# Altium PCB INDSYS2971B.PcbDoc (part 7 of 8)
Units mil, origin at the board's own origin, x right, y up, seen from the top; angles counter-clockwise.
Board outline 6450 x 5820 mil, 6 copper layers (Top Layer, Int1 (PGND), Int2 (AGND), Int3 (Signal), Int4 (PGND), Bottom Layer), stack 70.536 mil thick; 787 components, 431 nets, 2530 pads, 2497 vias.
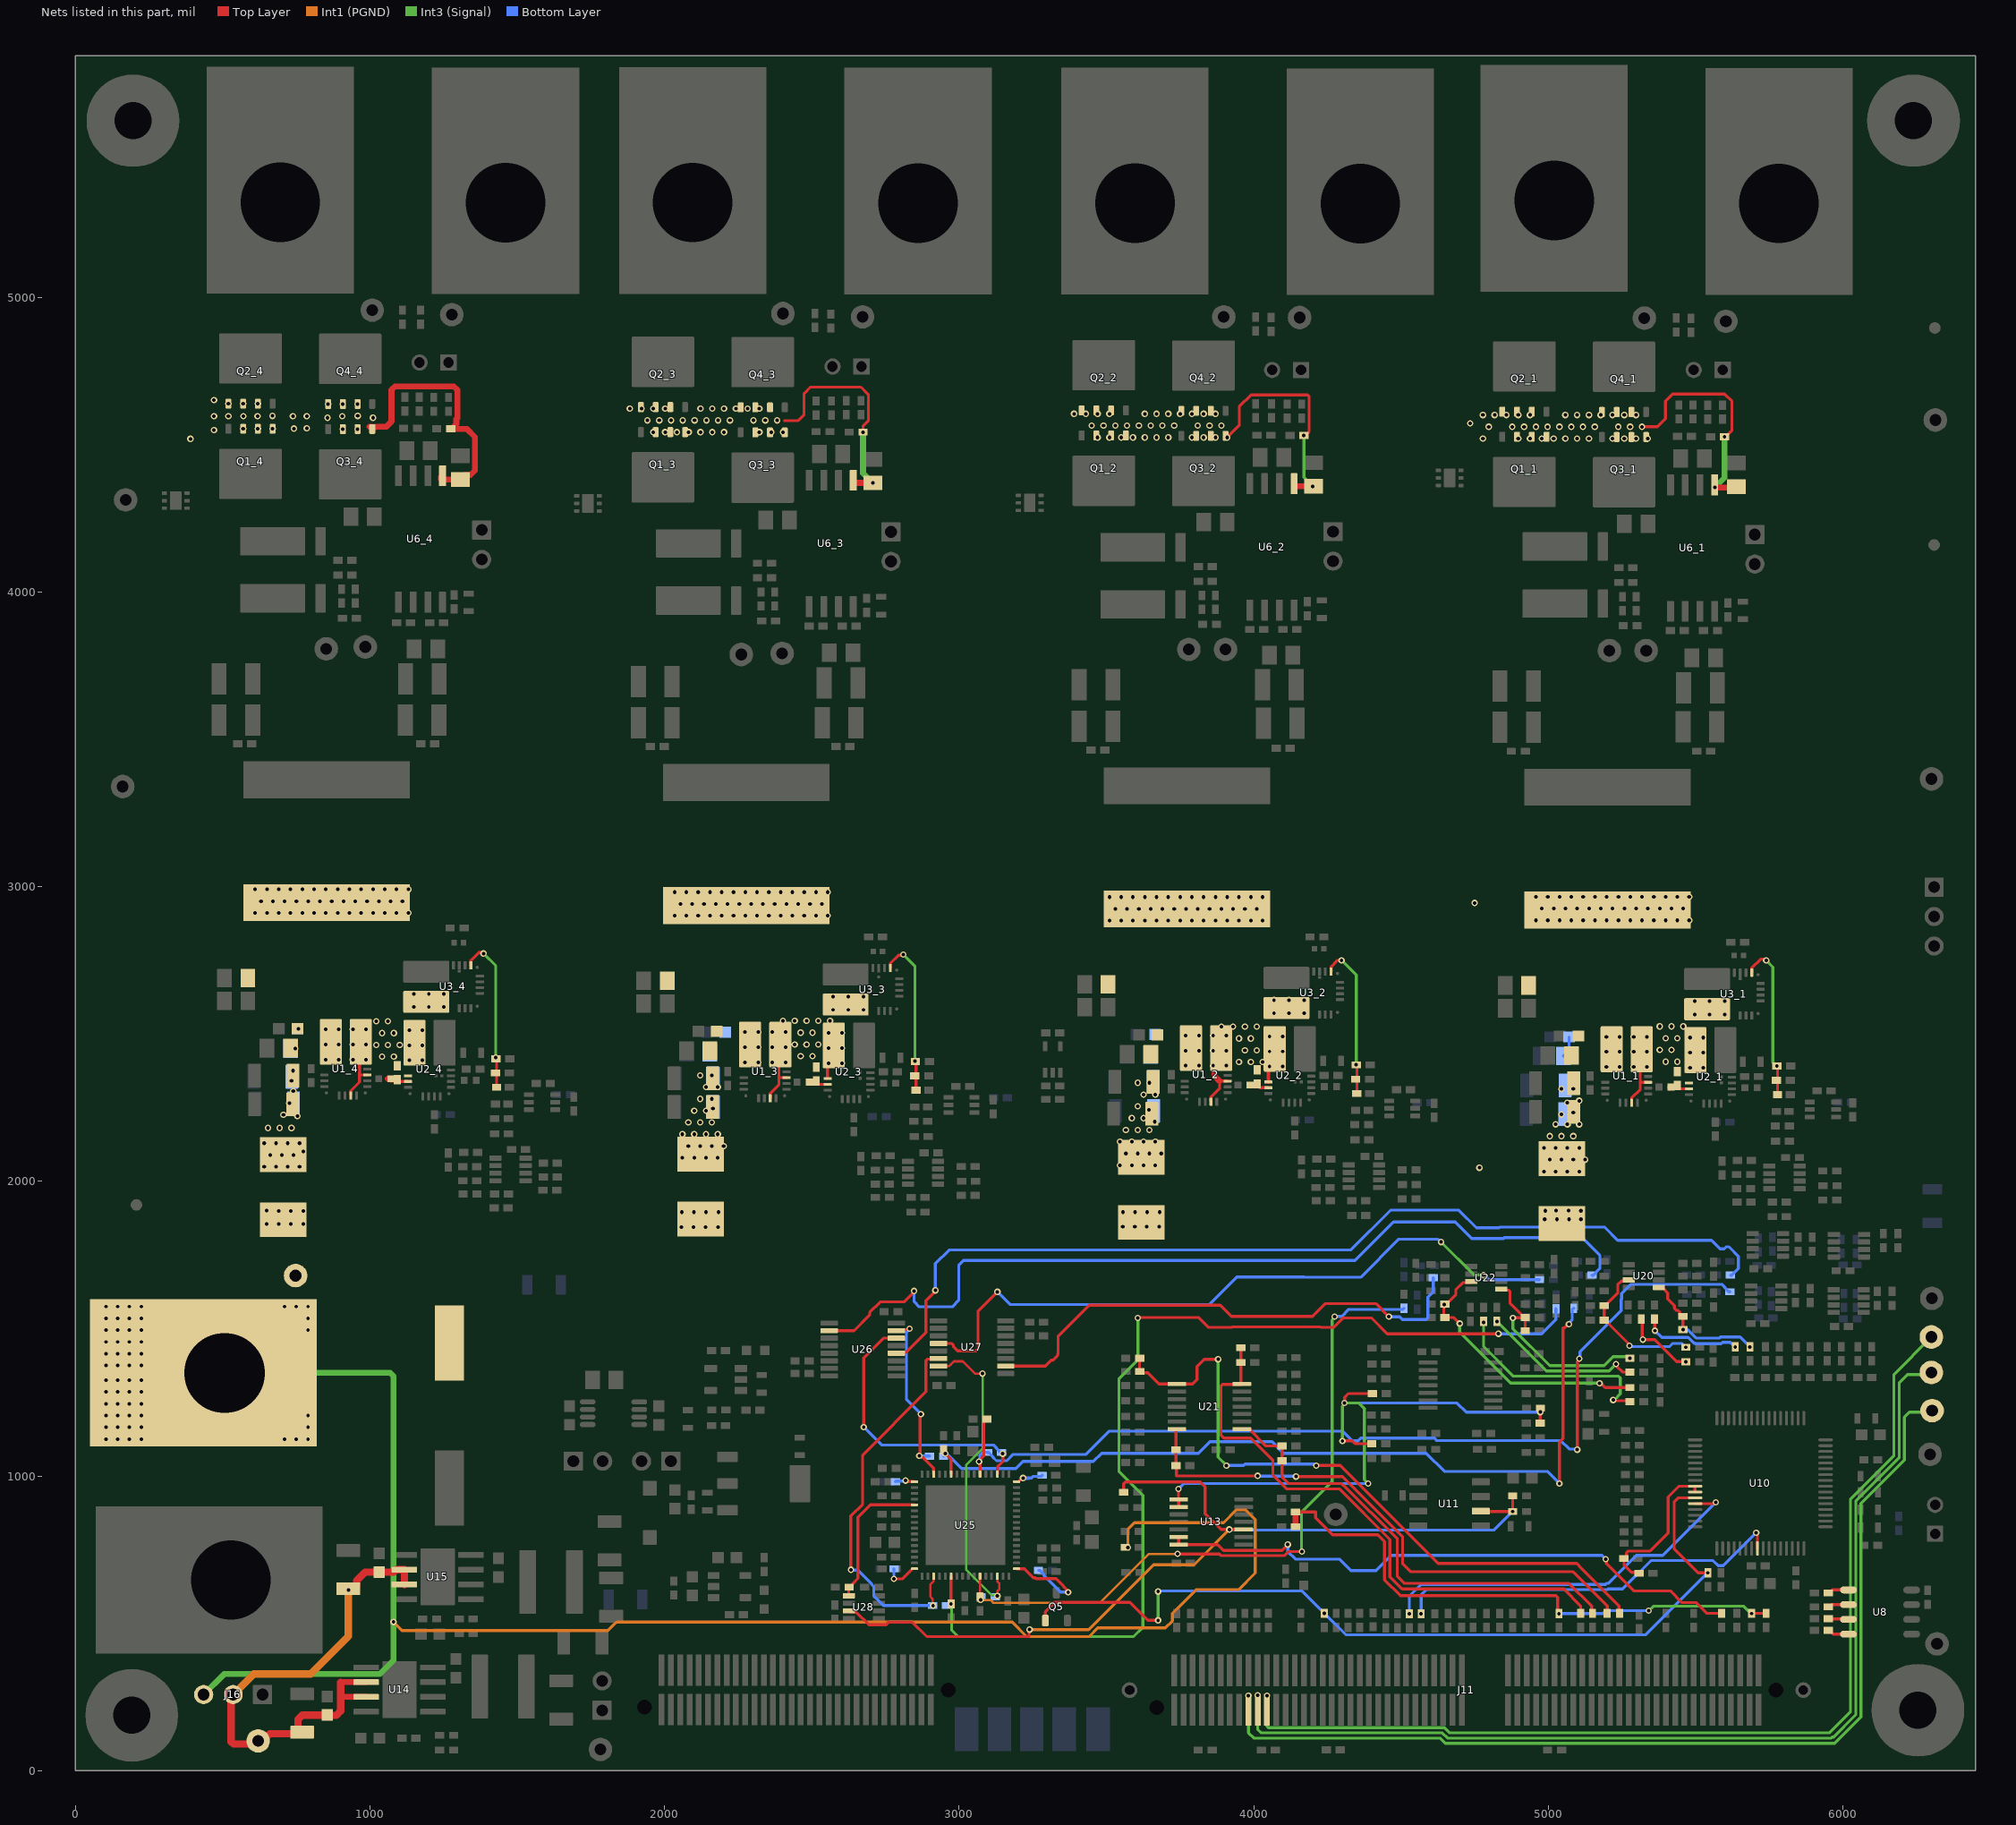
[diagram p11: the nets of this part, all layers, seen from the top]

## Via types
v1: diameter 22, hole 12.5, Top Layer to Bottom Layer, 873 vias
v2: diameter 22, hole 12, Top Layer to Bottom Layer, tented both sides, 788 vias
v3: diameter 22, hole 12, Top Layer to Bottom Layer, 586 vias
v4: diameter 22, hole 12.5, Top Layer to Bottom Layer, tented both sides, 249 vias
v5: diameter 24, hole 12, Top Layer to Bottom Layer, tented both sides, 1 vias

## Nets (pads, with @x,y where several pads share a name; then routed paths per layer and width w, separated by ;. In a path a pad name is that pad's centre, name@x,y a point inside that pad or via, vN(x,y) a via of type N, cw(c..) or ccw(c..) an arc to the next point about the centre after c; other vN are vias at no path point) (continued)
PWMLB_1: C114_1.1 D5_1.1 R193_1.2 U3_1.2 | length 552.5
  Top Layer w10: U3_1.2@5690.77,2708.35 5690.84,2708.43 5690.84,2724.5 5720.76,2754.41 5735.73,2754.41 v2(5740,2750.14) ; v2(5776.13,2391.3) 5778.28,2391.3 D5_1.1@5778.28,2294.21
  Int3 (Signal) w10: v2(5740,2750.14) 5762.83,2727.32 5762.83,2404.6 v2(5776.13,2391.3)
PWMLB_2: C114_2.1 D5_2.1 R193_2.2 U3_2.2 | length 532.2
  Top Layer w10: U3_2.2@4262.77,2712.35 4262.84,2712.43 4262.84,2728.49 4284.49,2750.14 v2(4298.2,2750.14) ; D5_2.1@4350.28,2298.21 C114_2.1@4350.28,2395.3
  Int3 (Signal) w10: v2(4298.2,2750.14) 4347.95,2700.39 v2(4347.95,2396.17)
PWMLB_3: C114_3.1 D5_3.1 R193_3.2 U3_3.2 | length 547.8
  Top Layer w10: U3_3.2@2766.16,2723.96 2766.24,2724.03 2766.24,2740.1 2793.99,2767.85 2807.71,2767.85 v2(2810,2770.14) ; D5_3.1@2853.67,2309.82 C114_3.1@2853.67,2406.91
  Int3 (Signal) w10: v2(2810,2770.14) 2850,2730.14 v2(2850,2408.36)
PWMLB_4: C114_4.1 D5_4.1 R193_4.2 U3_4.2 | length 541.2
  Top Layer w10: U3_4.2@1342.14,2733.35 1342.22,2733.43 1342.22,2749.49 1371.55,2778.82 1374.54,2775.83 1382.82,2775.83 v2(1385.12,2773.54) ; D5_4.1@1429.65,2319.21 C114_4.1@1429.65,2416.3
  Int3 (Signal) w10: v2(1385.12,2773.54) 1426.52,2732.14 v2(1426.52,2420.01)
REF1V25: R177.2 R178.2 R185.2 R186.2 U13.1 U13.2 | length 2129.7
  Top Layer w10: v2(3744.57,956.27) 3744.57,921.7 U13.1@3745.47,920.79 U13.2@3745.47,895.2 ; v2(4301.19,1119.02) 4334.95,1119.02 4344.25,1109.72 R177.2@4400.83,1109.72 ; v2(4308.42,1247.64) 4308.42,1266.75 4321.39,1279.72 R178.2@4402.76,1279.72 ; R185.2@4972.95,1179.72 4972.78,1179.89 v2(4972.78,1216.95) 4972.78,1229.53 R186.2@4973.45,1230.21
  Int3 (Signal) w10: v2(4301.19,1119.02) 4301.19,1237.16 4308.42,1244.39 v2(4308.42,1247.64) 4356.9,1247.64 4375.24,1229.3 4375.24,988.02 v2(4388.67,974.58)
  Bottom Layer w10: v2(3744.57,956.27) 3762.44,974.14 4153.24,974.14 4153.68,974.58 v2(4388.67,974.58) ; v2(4308.42,1247.64) 4690.75,1247.64 4721.44,1216.95 v2(4972.78,1216.95)
REF2V5: R106.1 R107.2 R112.2 U11.6 U13.10 U28.3 | length 3208.7
  Top Layer w10: U28.3@2625.23,542.23 2629.09,538.37 2650.09,538.37 2693.56,494.9 2752.45,494.9 2761.57,504.02 2840.31,504.02 2889.42,454.92 3235.84,454.92 3236.92,456 3236.92,476.5 v2(3239.21,478.79) ; R112.2@3558.82,944.53 3558.82,974.29 3564.68,980.14 3818.49,980.14 3835.24,963.4 3835.24,872.14 3888.95,818.43 v2(3916.99,818.43) U13.10@3965.94,818.43 ; U11.6@4770.75,880.69 4771.96,879.49 v2(4879.09,879.49) R107.2@4879.09,932.76
  Int1 (PGND) w10: v2(3239.21,478.79) 3439.48,478.79 3659.79,699.1 3797.66,699.1 v2(3916.99,818.43)
  Bottom Layer w10: v2(3916.99,818.43) 3918.68,816.73 4816.34,816.73 v2(4879.09,879.49)
REF2V5_C2K: C68.2 R36.1 R46.2 R111.2 R113.1 | length 1926.9
  Top Layer w10: R113.1@4141.85,878.19 4209.83,878.19 4209.83,858 4267.09,800.73 4420.79,800.73 4444.37,777.15 4444.37,647.75 4498.32,593.8 5026.17,593.8 5032.02,587.94 R46.2@5032.02,537.21 ; R36.1@5688.46,535.2 v2(5690.6,533.06) 5691.3,533.77 C68.2@5740,533.77
  Top Layer w20: R111.2@4141.85,827.92 R113.1@4141.85,878.19
  Int3 (Signal) w10: v2(5340.85,542.79) 5356.21,558.14 5663.38,558.14 5688.47,533.06 v2(5690.6,533.06)
  Bottom Layer w10: v2(5036.34,532.9) 5184.91,532.9 5194.79,542.79 v2(5340.85,542.79)
REn: R58.2 U8.2 | length 71.8
  Top Layer w10: R58.2@5950.45,555.79 5954.38,555.79 5961.81,563.22 U8.2@6019.17,563.22
RSTn: Q5.1 R69.1 R84.1 U10.11 | length 2949.6
  Top Layer w10: Q5.1@3292.6,509.28 3292.6,538.7 3325.1,571.21 3579.08,571.21 3640.26,510.03 v2(3675.37,510.03) ; U10.11@5498.54,925.93 5498.46,925.85 5442.26,925.85 5427.36,910.96 5427.36,752.78 5480.11,700.03 5508.73,671.41 v2(5541.97,671.41)
  Int3 (Signal) w10: v2(3675.37,510.03) v2(3675.37,607.69)
  Bottom Layer w10: v2(3675.37,607.69) 3677.21,609.53 4164.24,609.53 v2(4240,533.77) 4312.6,461.16 5331.31,461.16 v2@5542.65,672.5
SCLK: R61.1 U10.12 | length 1303.5
  Top Layer w10: U10.12@5498.54,906.25 v2@5569.16,906.25
  Bottom Layer w10: v2(4528.31,532.28) 4528.31,592.34 4568.24,632.27 5194.48,632.27 5197.72,635.51 5203.19,635.51 5298.72,731.03 5389.24,731.03 v2(5569.16,910.96)
SDOA: R59.1 U10.24 | length 1359.7
  Top Layer w10: v2(5705.89,807.54) 5705.89,804.29 5710.16,800.02 U10.24@5710.16,753.69
  Bottom Layer w10: v2(4568.31,532.28) 4568.31,596.53 4586.17,614.4 5201.88,614.4 5203.89,616.4 5252.34,616.4 5349.1,713.16 5559.26,713.16 5577.13,695.29 5593.64,695.29 v2(5705.89,807.54)
SHDNn: R60.2 U8.3 | length 69.8
  Top Layer w10: R60.2@5950.45,515.79 5951.73,514.5 6017.88,514.5 U8.3@6019.17,513.22
SNSP_1: R235.2 U26.12 | length 3327.7
  Top Layer w10: U26.12@2786.82,1416.59 2790.68,1420.45 2820.54,1420.45 2887.36,1487.27 2887.36,1594.76 2919.24,1626.63 v2(2919.24,1629.93)
  Bottom Layer w10: v2(2919.24,1629.93) 2919.24,1720.71 2965.54,1767.02 4329.12,1767.02 4464.49,1902.38 4695.84,1902.38 4756.11,1842.12 4833.55,1842.12 4836.19,1844.76 5191.45,1844.76 5236.07,1800.14 5553.69,1800.14 5582.83,1771 5597.64,1771 5604.61,1777.97 5612.9,1777.97 5645.28,1745.58 5645.28,1704.57 5622.61,1681.9 R235.2@5618.68,1681.9
SNSP_2: R237.2 U26.2 | length 3042.3
  Top Layer w10: U26.2@2558.48,1493.36 2643.2,1493.36 2696.22,1546.38 2696.22,1554.76 2732.46,1591.01 2813.14,1591.01 2847.06,1624.94 v2(2847.06,1628.24)
  Bottom Layer w10: v2(2847.06,1628.24) 2847.06,1591.23 2864.15,1574.14 2976.75,1574.14 2998.47,1595.86 2998.47,1714.73 3015,1731.27 4343.93,1731.27 4474.93,1862.27 4684.27,1862.27 4740.41,1806.14 4848.12,1806.14 4851,1809.01 5044.28,1809.01 5048.79,1804.5 5119.97,1804.5 5175.31,1749.15 5175.31,1704.25 5152.97,1681.9 R237.2@5149.03,1681.9
SNSP_3: R244.2 U27.12 | length 2379.1
  Top Layer w10: U27.12@2929.76,1449.94 2974.29,1449.94 2980.57,1443.66 2980.57,1438.51 2994.56,1424.52 3057.21,1424.52 3063.87,1431.19 3063.87,1559.09 v2(3129.8,1625.02)
  Int3 (Signal) w10: v2(4636.13,1794.08) 4747.11,1683.1 4778.75,1683.1 v2(4780.43,1681.42)
  Bottom Layer w10: v2(3129.8,1625.02) 3172.64,1582.19 3849.93,1582.19 3942.77,1675.02 4170.29,1675.02 4170.81,1674.5 4362.99,1674.5 4492.34,1803.85 4624.27,1803.85 4634.04,1794.08 v2(4636.13,1794.08) ; v2(4780.43,1681.42) 4783.67,1681.42 4799,1666.09 R244.2@4970.29,1666.09
SNSP_4: R246.2 U27.2 | length 1758.6
  Top Layer w10: U27.2@3158.11,1373.17 3293.29,1373.17 3312.58,1392.45 3317.77,1392.45 3334.09,1408.78 3334.09,1413.97 3335.94,1415.82 3335.94,1474.74 3441.07,1579.87 3885.92,1579.87 3923.99,1541.81 4200.1,1541.81 4243.5,1585.21 4414.48,1585.21 v2(4459,1540.69)
  Bottom Layer w10: v2(4459,1540.69) 4459.79,1539.89 4496,1539.89 4504.51,1531.39 4585.39,1531.39 4591.25,1537.24 4591.25,1607.62 4591.99,1607.62 4609.3,1624.94 R246.2@4609.3,1673.12
Source_1: C34_1.2 Q1_1.1 Q1_1.2 Q1_1.3 Q2_1.1 Q2_1.2 Q2_1.3 Q3_1.1 Q3_1.2 Q3_1.3 Q4_1.1 Q4_1.2 Q4_1.3 R28_1.1 U6_1.5 | length 780.4
  Top Layer w10: v1(5318,4561.14) 5370.53,4561.14 5398,4588.62 5398,4648.14 5422.5,4672.65 5598.37,4672.65 5623.54,4647.48 5623.54,4548.68 5602.28,4527.42 v2(5598.34,4527.42)
  Top Layer w20: v2(5565.91,4356.08) 5566.81,4355.17 C34_1.2@5631.3,4355.17
  Int3 (Signal) w20: v2(5565.91,4356.08) 5598.34,4388.52 v2(5598.34,4527.42)
  other v1: 4778,4521.14 4898,4521.14 4938,4521.14 4978,4521.14 5018,4521.14 5058,4521.14 5098,4521.14 5138,4521.14 5218,4521.14 5258,4521.14 5298,4521.14 5338,4521.14 4798,4561.14 4878,4561.14 4918,4561.14 4958,4561.14 4998,4561.14 5038,4561.14 5078,4561.14 5118,4561.14 5158,4561.14 5238,4561.14 5278,4561.14 4778,4601.14 4818,4601.14 4858,4601.14 4898,4601.14 4938,4601.14 5058,4601.14 5098,4601.14 5138,4601.14 5178,4601.14 5218,4601.14 5258,4601.14 5298,4601.14
  other v2: 4735,4572.98
Source_2: C34_2.2 Q1_2.1 Q1_2.2 Q1_2.3 Q2_2.1 Q2_2.2 Q2_2.3 Q3_2.1 Q3_2.2 Q3_2.3 Q4_2.1 Q4_2.2 Q4_2.3 R28_2.1 U6_2.5 | length 774.9
  Top Layer w10: v1(3910,4525.14) 3950.92,4566.06 3950.92,4629.15 3991.13,4669.36 4182.28,4669.36 4188.13,4663.5 4188.13,4545.28 4174.28,4531.42 v2(4170.34,4531.42)
  Top Layer w20: U6_2.5@4137,4368.07 4137,4360.98 4138.81,4359.17 v2(4200.35,4359.17)
  Int3 (Signal) w10: v2(4170.34,4531.42) 4170.34,4389.18 v2(4200.35,4359.17)
  other v1: 3470,4525.14 3510,4525.14 3550,4525.14 3590,4525.14 3630,4525.14 3670,4525.14 3710,4525.14 3790,4525.14 3830,4525.14 3870,4525.14 3450,4565.14 3490,4565.14 3530,4565.14 3570,4565.14 3610,4565.14 3650,4565.14 3690,4565.14 3730,4565.14 3810,4565.14 3850,4565.14 3890,4565.14 3390,4605.14 3430,4605.14 3470,4605.14 3510,4605.14 3630,4605.14 3670,4605.14 3710,4605.14 3750,4605.14 3790,4605.14 3830,4605.14 3870,4605.14
Source_3: C34_3.2 Q1_3.1 Q1_3.2 Q1_3.3 Q2_3.1 Q2_3.2 Q2_3.3 Q3_3.1 Q3_3.2 Q3_3.3 Q4_3.1 Q4_3.2 Q4_3.3 R28_3.1 U6_3.5 | length 780.8
  Top Layer w10: 2406.17,4582.1 2453.63,4582.1 2473.39,4601.86 2473.39,4674.39 2494.87,4695.87 2666.15,4695.87 2691.53,4670.49 2691.53,4581.47 2683.8,4573.74 2682.98,4573.74 2673.73,4564.49 v2(2673.73,4543.03)
  Top Layer w20: U6_3.5@2640.39,4379.68 2640.39,4372.59 2642.2,4370.78 v2(2706.69,4370.78)
  Int3 (Signal) w20: v2(2673.73,4543.03) 2673.73,4403.74 v2(2706.69,4370.78)
  other v1: 1961.67,4542.92 2001.67,4542.92 2041.67,4542.92 2081.67,4542.92 2121.67,4542.92 2161.67,4542.92 2201.67,4542.92 2321.67,4542.92 2361.67,4542.92 2401.67,4542.92 1941.67,4582.92 1981.67,4582.92 2021.67,4582.92 2061.67,4582.92 2101.67,4582.92 2141.67,4582.92 2181.67,4582.92 2221.67,4582.92 2301.67,4582.92 2341.67,4582.92 2381.67,4582.92 1881.67,4622.92 1921.67,4622.92 1961.67,4622.92 2001.67,4622.92 2121.67,4622.92 2161.67,4622.92 2201.67,4622.92 2241.67,4622.92 2281.67,4622.92 2321.67,4622.92
Source_4: C34_4.2 Q1_4.1 Q1_4.2 Q1_4.3 Q2_4.1 Q2_4.2 Q2_4.3 Q3_4.1 Q3_4.2 Q3_4.3 Q4_4.1 Q4_4.2 Q4_4.3 R28_4.1 U6_4.5 | length 906.9
  Top Layer w20: Q3_4.1@998,4561.14 Q3_4.1@1007.36,4561.14 ; Q3_4.1@1007.36,4560.36 1018.33,4560.36 1019.12,4561.14 1054.47,4561.14 1072.61,4579.29 1072.61,4686.6 1084.32,4698.31 1284.42,4698.31 1296.13,4686.6 1296.13,4590.73 1292.91,4587.51 1292.91,4570 R28_4.1@1277.28,4554.36 ; U6_4.5@1240,4391.01 1240,4383.92 1241.81,4382.11 C34_4.2@1306.3,4382.11 1321.3,4397.11 1340.24,4397.11 1355.67,4412.55 1355.67,4526.36 1327.67,4554.36 R28_4.1@1277.28,4554.36 ; R28_4.1@1273.34,4554.36 R28_4.1@1277.28,4554.36
  other v2: 390,4520.14
  other v4: 470,4550.25 907.36,4553.43 957.36,4553.43 569,4554.43 619,4554.43 669,4554.43 741.33,4555.09 785,4555.81 855.49,4591.84 1009.77,4591.84 470,4597.16 519,4597.16 569.77,4597.16 618,4597.16 738,4597.16 785,4597.16 905.76,4597.16 668.76,4598.1 958,4598.1 857.36,4638.47 907.36,4638.47 957.36,4638.47 519,4639.47 569,4639.47 619,4639.47 470,4651.48
STARTA: R52.2 R89.1 U10.9 U10.10 | length 527.6
  Top Layer w10: R52.2@5308.67,670.14 5306.08,672.73 5283.08,672.73 5257.32,698.49 5257.32,719.2 R89.1@5256.38,720.14 5259.24,720.14 5266.05,726.96 5266.05,739.25 5271.91,745.1 5345.59,745.1 5406.68,806.19 5406.68,928.84 5443.14,965.3 U10.9@5498.54,965.3 U10.10@5498.54,945.62
SW_1: C23_1.1 L1_1.1 R3_1.2 U1_1.4 U1_1.6 U1_1.14 U2_1.7 U2_1.8 U3_1.7 | length 223
  Top Layer w10: U1_1.14@5282.92,2266.41 5283,2266.49 5283,2282.56 5312.37,2311.93 5312.37,2336.3 ; U1_1.6@5317.37,2448.5 5317.37,2378.86 5312.37,2373.86 5312.37,2336.38 5312.45,2336.3 U1_1.4@5339.02,2336.3
  other v1: 5398.39,2406.14 5438.39,2406.14 5378.39,2446.14 5418.39,2446.14 5398.39,2486.14 5438.39,2486.14 5378.39,2526.14 5418.39,2526.14 5458.39,2526.14 4958.39,2886.14 4998.39,2886.14 5038.39,2886.14 5078.39,2886.14 5118.39,2886.14 5158.39,2886.14 5198.39,2886.14 5238.39,2886.14 5278.39,2886.14 5318.39,2886.14 5358.39,2886.14 5398.39,2886.14 5438.39,2886.14 5478.39,2886.14 4978.39,2926.14 5018.39,2926.14 5058.39,2926.14 5098.39,2926.14 5138.39,2926.14 5178.39,2926.14 5218.39,2926.14 5258.39,2926.14 5298.39,2926.14 5338.39,2926.14 5378.39,2926.14 5418.39,2926.14 5458.39,2926.14 4958.39,2966.14 4998.39,2966.14 5038.39,2966.14 5078.39,2966.14 5118.39,2966.14 5158.39,2966.14 5198.39,2966.14 5238.39,2966.14 5278.39,2966.14 5318.39,2966.14 5358.39,2966.14 5398.39,2966.14 5438.39,2966.14 5478.39,2966.14
  other v2: 4750,2945.14
  other v4: 5481.53,2385.74 5526.41,2385.74 5290.21,2388.46 5335.09,2388.46 5481.53,2436.92 5526.41,2436.92 5290.21,2439.64 5335.09,2439.64 5481.53,2488.1 5526.41,2488.1 5290.21,2490.82 5335.09,2490.82 5496.87,2566.61 5548.05,2566.61 5599.23,2566.61 5496.87,2611.5 5548.05,2611.5 5599.23,2611.5
SW_2: C23_2.1 L1_2.1 R3_2.2 U1_2.4 U1_2.6 U1_2.14 U2_2.7 U2_2.8 U3_2.7 | length 224.4
  Top Layer w10: U1_2.14@3854.92,2270.42 3855,2270.49 3855,2286.56 3884.37,2315.93 3884.37,2340.38 3884.45,2340.3 U1_2.4@3911.02,2340.3
  Top Layer w12: U2_2.8@4049.59,2337.57 4049.59,2385.8 v2(4053.53,2389.74)
  Top Layer w20: v2(3862.21,2392.46) 3867.24,2387.42 3867.24,2357.5 3884.37,2340.38 ; U2_2.7@4053.16,2389.37 v2(4053.53,2389.74)
  other v1: 3950,2405.14 3990,2405.14 4030,2405.14 3970,2445.14 4010,2445.14 3950,2485.14 3990,2485.14 3890,2525.14 3930,2525.14 3970,2525.14 4010,2525.14 3510,2885.14 3550,2885.14 3590,2885.14 3630,2885.14 3670,2885.14 3710,2885.14 3750,2885.14 3790,2885.14 3830,2885.14 3870,2885.14 3910,2885.14 3950,2885.14 3990,2885.14 4030,2885.14 3530,2925.14 3570,2925.14 3610,2925.14 3650,2925.14 3690,2925.14 3730,2925.14 3770,2925.14 3810,2925.14 3850,2925.14 3890,2925.14 3930,2925.14 3970,2925.14 4010,2925.14 3510,2965.14 3550,2965.14 3590,2965.14 3630,2965.14 3670,2965.14 3710,2965.14 3750,2965.14 3790,2965.14 3830,2965.14 3870,2965.14 3910,2965.14 3950,2965.14 3990,2965.14 4030,2965.14
  other v2: 4098.41,2389.74 3907.09,2392.46 4053.53,2440.92 4098.41,2440.92 3862.21,2443.64 3907.09,2443.64 4053.53,2492.1 4098.41,2492.1 3862.21,2494.82 3907.09,2494.82 4068.87,2570.61 4120.05,2570.61 4171.23,2570.61 4068.87,2615.5 4120.05,2615.5 4171.23,2615.5
SW_3: C23_3.1 L1_3.1 R3_3.2 U1_3.4 U1_3.6 U1_3.14 U2_3.7 U2_3.8 U3_3.7 | length 229.4
  Top Layer w10: U1_3.14@2358.31,2282.02 2358.39,2282.1 2358.39,2298.17 2387.76,2327.54 2387.76,2351.98 ; v2(2365.6,2404.07) 2375.05,2404.07 2387.76,2391.35 2387.76,2351.98 ; U1_3.4@2414.42,2351.91 2387.84,2351.9 2387.76,2351.98 ; U2_3.8@2552.98,2349.18 2552.98,2397.41 v2(2556.92,2401.35)
  other v1: 2461.69,2424.63 2501.69,2424.63 2441.69,2464.63 2481.69,2464.63 2521.69,2464.63 2461.69,2504.63 2501.69,2504.63 2401.69,2544.63 2441.69,2544.63 2481.69,2544.63 2521.69,2544.63 2561.69,2544.63 2033.78,2901.75 2073.78,2901.75 2113.78,2901.75 2153.78,2901.75 2193.78,2901.75 2233.78,2901.75 2273.78,2901.75 2313.78,2901.75 2353.78,2901.75 2393.78,2901.75 2433.78,2901.75 2473.78,2901.75 2513.78,2901.75 2553.78,2901.75 2053.78,2941.75 2093.78,2941.75 2133.78,2941.75 2173.78,2941.75 2213.78,2941.75 2253.78,2941.75 2293.78,2941.75 2333.78,2941.75 2373.78,2941.75 2413.78,2941.75 2453.78,2941.75 2493.78,2941.75 2533.78,2941.75 2033.78,2981.75 2073.78,2981.75 2113.78,2981.75 2153.78,2981.75 2193.78,2981.75 2233.78,2981.75 2273.78,2981.75 2313.78,2981.75 2353.78,2981.75 2393.78,2981.75 2433.78,2981.75 2473.78,2981.75 2513.78,2981.75 2553.78,2981.75
  other v2: 2601.8,2401.35 2410.48,2404.07 2556.92,2452.53 2601.8,2452.53 2365.6,2455.25 2410.48,2455.25 2556.92,2503.71 2601.8,2503.71 2365.6,2506.43 2410.48,2506.43 2572.26,2582.22 2623.44,2582.22 2674.62,2582.22 2572.26,2627.1 2623.44,2627.1 2674.62,2627.1
SW_4: C23_4.1 L1_4.1 R3_4.2 U1_4.4 U1_4.6 U1_4.14 U2_4.7 U2_4.8 U3_4.7 | length 245.8
  Top Layer w10: U1_4.14@934.3,2291.42 934.38,2291.49 934.38,2307.56 963.75,2336.93 963.75,2361.38 ; v2(941.58,2413.46) 946.4,2413.46 U1_4.6@959.11,2400.75 ; U1_4.6@968.75,2473.5 963.75,2468.5 963.75,2361.38 ; U1_4.4@990.4,2361.3 963.83,2361.3 963.75,2361.38
  other v1: 1040.61,2423.16 1080.61,2423.16 1020.61,2463.16 1060.61,2463.16 1100.61,2463.16 1040.61,2503.16 1080.61,2503.16 1020.61,2543.16 1060.61,2543.16 609.77,2911.14 649.77,2911.14 689.77,2911.14 729.77,2911.14 769.77,2911.14 809.77,2911.14 849.77,2911.14 889.77,2911.14 929.77,2911.14 969.77,2911.14 1009.77,2911.14 1049.77,2911.14 1089.77,2911.14 1129.77,2911.14 629.77,2951.14 669.77,2951.14 709.77,2951.14 749.77,2951.14 789.77,2951.14 829.77,2951.14 869.77,2951.14 909.77,2951.14 949.77,2951.14 989.77,2951.14 1029.77,2951.14 1069.77,2951.14 1109.77,2951.14 609.77,2991.14 649.77,2991.14 689.77,2991.14 729.77,2991.14 769.77,2991.14 809.77,2991.14 849.77,2991.14 889.77,2991.14 929.77,2991.14 969.77,2991.14 1009.77,2991.14 1049.77,2991.14 1089.77,2991.14 1129.77,2991.14
  other v2: 1132.91,2410.74 1177.79,2410.74 986.47,2413.46 1132.91,2461.92 1177.79,2461.92 941.58,2464.64 986.47,2464.64 1132.91,2513.1 1177.79,2513.1 941.58,2515.82 986.47,2515.82 1148.25,2591.61 1199.43,2591.61 1250.61,2591.61 1148.25,2636.5 1199.43,2636.5 1250.61,2636.5
TEST1: J11.100 TP9.1 | length 3560.1
  Top Layer w10: J11.100@4044.96,206.29 v2(4044.96,254.44)
  Int3 (Signal) w10: v2@4043.72,255.68 v2(4044.96,254.44) 4043.72,253.2 4043.72,151.75 4049.58,145.89 4647.81,145.89 4665.53,128.18 5953.53,128.18 6026.1,200.74 6026.1,921.84 6173.5,1069.24 6173.5,1344.62 TP9.1@6300.7,1471.81
TEST2: J11.102 TP10.1 | length 3553.4
  Top Layer w10: v2(4013.23,255.31) 4013.35,255.19 4013.35,206.4 J11.102@4013.46,206.29
  Int3 (Signal) w10: v2@4013.23,256.93 v2(4013.23,255.31) 4013.23,140.45 4025.66,128.02 4640.41,128.02 4658.13,110.3 5960.94,110.3 5964.69,114.06 5968.91,114.06 6043.98,189.12 6043.98,914.43 6191.38,1061.83 6191.38,1315.99 6220,1344.62 6293.79,1344.62 TP10.1@6300.7,1351.52
TEST3: J11.104 TP17.1 | length 3488
  Top Layer w10: J11.104@3981.97,206.29 v2(3981.97,254.44)
  Int3 (Signal) w10: v2(3981.97,254.44) 3981.97,128.18 4000,110.14 4633.01,110.14 4650.88,92.27 5972.4,92.27 6061.85,181.72 6061.85,906.68 6205,1049.83 6205,1050.18 6209.25,1054.43 6209.25,1199.4 6226.26,1216.41 6297.6,1216.41 TP17.1@6303.04,1221.85
UARTRX: R64.2 U8.1 | length 73
  Top Layer w10: R64.2@5950.45,602.87 5954.38,602.87 5964.73,613.22 U8.1@6019.17,613.22
UARTTX: R62.2 U8.4 | length 73.9
  Top Layer w10: R62.2@5950.45,475.79 5954.38,475.79 5966.95,463.22 U8.4@6019.17,463.22
V_HV: C1.1 F1_1.2 F1_2.2 F1_3.2 F1_4.2 J1.1 J16.3 R115.2 T1.1 TP1.1 | length 6037.3
  Top Layer w10: R115.2@3563.82,758.23 3571.56,758.23 v2(3572.61,757.18)
  Int3 (Signal) w20: J16.3@434.88,257.98 504.59,327.69 1032.32,327.69 1079.86,375.23 1079.86,1338.43 1068.14,1350.14 T1.1@508,1350.14 J1.1@504.06,1350.14
  Int1 (PGND) w10: v2(1079.4,504.35) 1108.6,475.14 1807.27,475.14 1836.47,504.35 3179.89,504.35 3229.33,454.92 3440.88,454.92 3470.17,484.21 3699.92,484.21 3723.57,507.85 3723.57,533.06 3804.86,614.35 3948.46,614.35 4004.73,670.62 4004.73,852.51 3972.29,884.95 3941.15,884.95 3897.94,841.73 3595.35,841.73 3572.61,818.99 v2(3572.61,757.18)
  other v3: 103,1125.14 143,1125.14 183,1125.14 223,1125.14 709.27,1125.14 749.27,1125.14 789.27,1125.14 103,1165.14 143,1165.14 183,1165.14 223,1165.14 789.27,1165.14 103,1205.14 143,1205.14 183,1205.14 223,1205.14 789.27,1205.14 103,1245.14 143,1245.14 183,1245.14 223,1245.14 103,1285.14 143,1285.14 183,1285.14 223,1285.14 103,1325.14 143,1325.14 183,1325.14 223,1325.14 103,1375.14 143,1375.14 183,1375.14 223,1375.14 103,1415.14 143,1415.14 183,1415.14 223,1415.14 103,1455.14 143,1455.14 183,1455.14 223,1455.14 103,1495.14 143,1495.14 183,1495.14 223,1495.14 789.27,1495.14 103,1535.14 143,1535.14 183,1535.14 223,1535.14 789.27,1535.14 103,1575.14 143,1575.14 183,1575.14 223,1575.14 709.27,1575.14 749.27,1575.14 789.27,1575.14
  other v4: 2057.4,1844.2 2098.48,1844.2 2138.91,1844.2 2181.56,1844.2 3555.4,1846.32 3596.48,1846.32 3636.91,1846.32 3679.56,1846.32 648.9,1855.14 689.98,1855.14 730.41,1855.14 773.06,1855.14 4987.78,1871.36 5029.51,1871.36 5070.14,1871.36 5110.73,1871.36 3556.41,1895.59 3597.5,1895.59 3637.92,1895.59 3680.58,1895.59 2058.69,1895.76 2099.77,1895.76 2140.2,1895.76 2182.85,1895.76 689.98,1899.14 730.41,1899.14 773.06,1900.01 4990.26,1900.14 5110.73,1900.14 648.9,1901.54 5026.51,1900.86 5068.48,1900.86
V_HV_1: C2_1.2 C3_1.1 C4_1.2 C5_1.1 C6_1.2 C7_1.1 C8_1.1 C9_1.2 F1_1.1 U1_1.7 | length 72.5
  Bottom Layer w10: C7_1.1@5051.9,2425.53 5070.27,2443.9 C8_1.1@5070.27,2490.47
  other v1: 4985.01,2033.66 5025.01,2033.66 5065.01,2033.66 5105.01,2033.66 5005.01,2073.66 5045.01,2073.66 5085.01,2073.66 5125.01,2073.66 4985.01,2113.66 5025.01,2113.66 5065.01,2113.66 5105.01,2113.66 5005.01,2153.66 5045.01,2153.66 5085.01,2153.66 5025.01,2193.66 5065.01,2193.66 5105.01,2193.66 5044.61,2227.03 5085.01,2233.66 5064.61,2267.03 5105.01,2273.66 5045.01,2313.66 5085.01,2313.66
  other v2: 4766.29,2046.16
  other v4: 5197.29,2388.46 5242.17,2388.46 5197.29,2439.64 5242.17,2439.64 5197.29,2490.82 5242.17,2490.82
V_HV_2: C2_2.2 C3_2.1 C4_2.2 C5_2.1 C6_2.2 C7_2.1 C8_2.1 C9_2.2 F1_2.1 U1_2.7
  other v1: 3546.06,2054.72 3586.06,2054.72 3626.06,2054.72 3666.06,2054.72 3566.06,2094.72 3606.06,2094.72 3646.06,2094.72 3686.06,2094.72 3546.06,2134.72 3586.06,2134.72 3626.06,2134.72 3666.06,2134.72 3566.06,2174.72 3606.06,2174.72 3646.06,2174.72 3663.82,2202.61 3586.06,2214.72 3626.06,2214.72 3643.82,2242.61 3606.06,2254.72 3626.06,2294.72 3666.06,2294.72 3606.06,2334.72 3646.06,2334.72
  other v2: 3769.29,2392.46 3814.17,2392.46 3769.29,2443.64 3814.17,2443.64 3769.29,2494.82 3814.17,2494.82
V_HV_3: C2_3.2 C3_3.1 C4_3.2 C5_3.1 C6_3.2 C7_3.1 C8_3.1 C9_3.2 F1_3.1 U1_3.7
  other v1: 2060.52,2079.84 2100.52,2079.84 2140.52,2079.84 2180.52,2079.84 2080.52,2119.84 2120.52,2119.84 2160.52,2119.84 2200.52,2119.84 2060.52,2159.84 2100.52,2159.84 2140.52,2159.84 2180.52,2159.84 2080.52,2199.84 2120.52,2199.84 2160.52,2199.84 2100.52,2239.84 2140.52,2239.84 2164.08,2246.98 2120.52,2279.84 2160.52,2279.84 2140.52,2319.84 2180.52,2319.84 2120.52,2359.84 2160.52,2359.84
  other v2: 2272.68,2404.07 2317.57,2404.07 2272.68,2455.25 2317.57,2455.25 2272.68,2506.43 2317.57,2506.43
V_HV_4: C2_4.2 C3_4.1 C4_4.2 C5_4.1 C6_4.2 C7_4.1 C8_4.1 C9_4.2 F1_4.1 U1_4.7
  other v1: 640.42,2049.47 680.42,2049.47 720.42,2049.47 760.42,2049.47 660.42,2089.47 700.42,2089.47 740.42,2089.47 773.17,2101.38 640.42,2129.47 680.42,2129.47 720.42,2129.47 760.42,2129.47 653.17,2181.38 693.17,2181.38 733.17,2181.38 753.17,2221.38 705.73,2225.69 725.73,2265.69 739.24,2306.37 733.17,2341.38
  other v2: 848.67,2413.46 893.55,2413.46 848.67,2464.64 893.55,2464.64 848.67,2515.82 893.55,2515.82
  other v4: 738.67,2375.52 745.95,2450.79 756.78,2517.74
VbatN1: R94.1 R139.2 | length 340.4
  Top Layer w10: R139.2@5360.92,1533.16 5361.51,1532.57 5361.51,1493.72 v2(5362.11,1493.12)
  Bottom Layer w10: v2(5362.11,1493.12) 5385.09,1470.14 5474.75,1470.14 5494.48,1450.42 5498.74,1450.42 5500.43,1448.73 5586.97,1448.73 5592.26,1454.02 5617.65,1454.02 5633.49,1438.18 v2(5634.8,1438.18)
VbatN2: R96.1 R151.2 | length 249.1
  Top Layer w10: R151.2@5315.92,1533.16 5318.85,1530.23 5318.85,1465.75 v2(5321.53,1463.07) 5361.46,1463.07 5436.22,1388.31 5466.2,1388.31 v2(5466.97,1387.55)
VbatN3: R98.1 R162.2 | length 545.9
  Top Layer w10: R162.2@4825.43,1524.5 v2(4826.11,1523.81) R162.2@4826.8,1523.12 ; v2(5230,1379.72) 5232.68,1377.04 5232.68,1371.65 5251.67,1352.66 R98.1@5276.97,1352.66
  Int3 (Signal) w10: v2(4826.11,1523.81) 4993.16,1356.77 5207.05,1356.77 v2(5230,1379.72)
VbatN4: R102.1 R175.2 | length 739.4
  Top Layer w10: v2(4780.43,1520.56) R175.2@4780.43,1524.5 ; v2(5220.43,1258.02) 5223.05,1255.4 5274.35,1255.4 R102.1@5276.97,1252.78
  Int3 (Signal) w10: v2(4780.43,1520.56) 4780.43,1439.72 4881.25,1338.89 5239.02,1338.89 5244.87,1333.03 5244.87,1278.83 5224.06,1258.02 v2(5220.43,1258.02)
VbatP1: C97.2 R93.1 R141.1 U20.1 | length 443.7
  Top Layer w10: U20.1@5375.58,1640.05 5387.39,1640.05 5391.25,1636.19 5391.25,1635.32 5405.39,1621.18 5405.39,1601.27 5425.74,1580.91 5428.67,1577.98 ccw(c5448.82,1577.98) 5428.67,1577.92 5428.67,1569.64 5436.22,1562.1 5440.69,1562.1 5446.55,1556.24 5446.55,1548.6 5453.36,1541.78 R141.1@5457.3,1541.78 v2(5457.3,1496.78)
  Bottom Layer w10: v2(5457.3,1496.78) 5457.78,1496.3 5473.58,1496.3 5481.87,1488.02 5482.15,1488.02 5501.88,1468.29 5581.25,1468.29 5584.86,1471.9 5651.09,1471.9 v2(5684.8,1438.18)
VbatP2: C101.2 R95.1 R150.1 U20.7 | length 514.3
  Top Layer w10: U20.7@5273.21,1665.64 5269.35,1661.78 5248.35,1661.78 5235.92,1649.35 5235.92,1620.74 5191.97,1576.78 R150.1@5189.68,1578.44 C101.2@5189.68,1528.44 5193.62,1528.44 5272.62,1449.43 5272.62,1444.95 v2(5275.3,1442.27)
  Bottom Layer w10: v2(5275.3,1442.27) 5277.6,1439.97 5286.08,1439.97 5286.86,1439.19 5411.82,1439.19 5422.45,1449.83 5454.06,1449.83 v2(5466.97,1436.92)
VbatP3: C103.2 R97.1 R164.1 U22.1 | length 724
  Top Layer w10: U22.1@4840.54,1634.58 4844.4,1630.72 4864.5,1630.72 4867.43,1627.79 4870.36,1624.86 ccw(c4917.45,1624.86) 4870.36,1624.76 4870.36,1585.63 4917.87,1538.12 4917.13,1537.39 4880.74,1537.39 v2(4880,1536.65) ; R164.1@4921.8,1493.12 C103.2@4921.8,1538.12 ; R97.1@5276.73,1400.14 v2(5276.97,1399.91)
  Int3 (Signal) w10: v2(4880,1536.65) 4880,1499.86 5005.22,1374.64 5189.74,1374.64 5219.7,1404.59 5265.11,1404.59 5267.5,1402.2 5274.67,1402.2 v2(5276.97,1399.91)
VbatP4: C108.2 R100.1 R174.1 U22.7 | length 925.4
  Top Layer w10: v2(4647.24,1581.31) C108.2@4649.05,1583.12 ; v2(4699.28,1517.46) 4678.61,1538.12 R174.1@4649.05,1538.12 4645.43,1541.74 4645.43,1579.5 C108.2@4649.05,1583.12 ; U22.7@4738.18,1660.17 4734.32,1656.31 4709.24,1656.31 4686.56,1633.63 4686.56,1616.7 4652.99,1583.12 C108.2@4649.05,1583.12 ; v2(5174.52,1315.02) 5178.31,1315.02 5193.3,1300.03 R100.1@5276.97,1300.03
  Int3 (Signal) w10: v2(4699.28,1517.46) 4699.28,1487.89 4872.15,1315.02 v2(5174.52,1315.02)
VCC_TOP_1: C23_1.2 R1_1.1 U2_1.9 | length 68.7
  Top Layer w10: C23_1.2@5436.58,2321.34 5444.03,2313.89 U2_1.9@5477.59,2313.89 U2_1.9@5477.51,2313.81
  Top Layer w20: R1_1.1@5412.83,2317.73 R1_1.1@5414.64,2319.54 ; R1_1.1@5414.64,2321.34 C23_1.2@5436.58,2321.34
VCC_TOP_2: C23_2.2 R1_2.1 U2_2.9 | length 69.7
  Top Layer w10: R1_2.1@3987.67,2327.16 C23_2.2@4011.57,2327.16 ; C23_2.2@4007.74,2327.16 C23_2.2@4011.57,2327.16 ; U2_2.9@4049.51,2317.81 U2_2.9@4049.59,2317.89 4020.84,2317.89 C23_2.2@4011.57,2327.16
VCC_TOP_3: C23_3.2 R1_3.1 U2_3.9 | length 68.9
  Top Layer w10: R1_3.1@2491.06,2336.64 2511.17,2336.64 C23_3.2@2514.88,2340.35 ; C23_3.2@2513.03,2338.26 2521.69,2329.6 2521.92,2329.6 2522.02,2329.5 U2_3.9@2552.98,2329.5
VCC_TOP_4: C23_4.2 R1_4.1 U2_4.9 | length 93.3
  Top Layer w10: C23_4.2@1092.08,2345.3 1098.49,2338.89 U2_4.9@1128.97,2338.89
  Top Layer w20: R1_4.1@1059.85,2348.84 1060.61,2348.08 C23_4.2@1091.32,2348.08 ; R1_4.1@1070.44,2346.05 1091.32,2346.05 C23_4.2@1092.08,2345.3
VEXT: C78.2 C79.2 C80.1 C81.1 J16.2 TP11.1 U14.2 U14.3 U15.2 U15.3 | length 1789.2
  Top Layer w20: 900,251.21 901.1,250.1 U14.3@986.81,250.1 ; 900,300.1 U14.2@986.81,300.1
  Top Layer w25: J16.2@527.83,254.14 527.83,98.33 536.02,90.14 TP11.1@620,90.14 ; TP11.1@620,100.82 634.88,100.82 659.25,125.18 755,125.18 755,174 769.64,188.65 C80.1@848.5,188.65 ; C80.1@854.7,187.66 885.36,187.66 900,202.31 900,251.21 900,300.1 ; C79.2@926.34,617.11 C79.2@928.82,617.11 ; C79.2@937.97,607.96 C79.2@928.82,617.11 ; U15.3@1116.32,632.07 U15.2@1116.32,682.07 1088.18,682.07 1079.86,673.76 C81.1@1030.87,673.76 982.98,673.76 954.19,644.97 954.19,626.27 945.04,617.11 C79.2@928.82,617.11
  Int1 (PGND) w25: J16.2@534.88,257.98 604.86,327.95 797.8,327.95 926.34,456.49 v2(926.34,613.18)
Vin: R41.2 U13.6 U13.7 | length 2046.6
  Top Layer w10: U13.6@3745.47,792.84 U13.7@3745.47,767.25 3876.9,767.25 3896.67,747.48 4095.7,747.48 v2(4115.64,767.42) ; v2@5195.33,718.02 v2(5195.08,717.77) 5197.37,715.48 5197.37,702.63 5289.86,610.14 5414.72,610.14 5454.72,570.14 5503.17,570.14 5539.55,533.77 R41.2@5588.27,533.77
  Bottom Layer w10: v2(4115.64,767.42) 4115.64,743.46 4141.32,717.77 4290.75,717.77 4329.51,679.02 4414.89,679.02 4466.9,731.03 5181.82,731.03 v2(5195.08,717.77)
VoutP1: C100.2 R42.2 R143.2 U21.1 | length 2322.3
  Top Layer w10: C100.2@3612.56,1399.93 3612.56,1356.21 R143.2@3613.62,1355.14 3618.83,1349.93 3640.83,1349.93 3678.46,1312.29 U21.1@3739.49,1312.29 3792.93,1312.29 3807.93,1327.29 3807.93,1372.24 3831.78,1396.1 v2(3879.02,1396.1) ; v2(4212.51,1035.52) 4293.97,1035.52 4626.12,703.37 5096.58,703.37 5104.2,695.75 5104.2,694.69 5240.24,558.66 5240.24,535.34 R42.2@5241.81,533.77
  Int3 (Signal) w10: v2(3879.02,1396.1) 3879.02,1063.98 v2(3907.48,1035.52)
  Bottom Layer w10: v2(3907.48,1035.52) 3965.81,1035.52 3970.76,1040.47 4204.31,1040.47 4209.26,1035.52 v2(4212.51,1035.52)
VoutP2: C102.2 R43.2 R154.2 U21.7 | length 1885.6
  Top Layer w10: U21.7@3739.49,1158.75 3737.99,1158.75 3736.1,1156.86 R154.2@3736.1,1089.14 C102.2@3736.1,1035.52 3737.51,1034.12 3737.51,1000.42 4013.23,1000.42 v2(4013.54,1000.73) ; v2(4143.35,998.02) 4301.77,998.02 4505.31,794.48 4505.31,703.29 4533.58,675.03 5084.33,675.03 5200,559.36 R43.2@5200,533.77
  Bottom Layer w10: v2(4013.54,1000.73) 4014.89,999.37 4141.99,999.37 v2(4143.35,998.02)
VoutP3: C106.2 R44.2 R165.2 U21.8 | length 1598
  Top Layer w10: U21.8@3959.96,1158.75 3984.57,1158.75 4041.49,1101.83 R165.2@4096.1,1101.83 C106.2@4096.1,1051.83 4096.1,996.67 4118.63,974.14 4297.93,974.14 4303.82,968.26 4306.25,968.26 4487.44,787.07 4487.44,659.86 4511.78,635.51 5070.4,635.51 5147.25,558.66 5147.25,536.51 R44.2@5150,533.77
VoutP4: C107.2 R45.2 R176.2 U21.14 | length 1952.6
  Top Layer w10: U21.14@3956.1,1314.18 C107.2@3956.1,1385.52 R176.2@3956.1,1435.52 ; U21.14@3959.96,1312.29 3958.89,1311.22 3894.54,1311.22 3888.69,1305.36 3888.69,1139.1 3899.17,1128.62 3989.42,1128.62 4065.14,1052.91 4065.14,1002.36 4111.22,956.27 4290.53,956.27 4462.24,784.56 4462.24,657.96 4503.81,616.4 5052.95,616.4 5110,559.36 R45.2@5110,533.77
VREF_5V: R251.2 U25.5 U28.1 | length 490.8
  Top Layer w10: U28.1@2625.23,593.41 2625.23,621.48 2629.17,621.48 2637.44,629.75 2637.44,633.68 2656.14,652.38 2656.14,859.28 2698.69,901.83 U25.5@2848.31,901.83
VSN1: C133.1 R220.2 R221.2 U25.54 | length 3320.6
  Top Layer w10: v2@3067.63,1045.58 3070.75,1042.46 U25.54@3070.75,1006.16 ; v2@3070.09,1048.02 v2@3070.09,1048.83 ; v2@3070.09,1054.2 3083.62,1067.73 3083.62,1186.66 3090.43,1193.47 R221.2@3094.37,1193.47 ; v2(5098.39,1089.27) 5098.39,1388.22 5105.44,1395.27 v2(5105.44,1398.51)
  Bottom Layer w10: v2(3067.63,1048.83) 3069.92,1051.13 3069.92,1068.75 3082.13,1080.96 3095.73,1080.96 C133.1@3096.54,1080.14 3100.47,1080.14 3115.16,1065.46 3115.16,1063 3126.3,1051.86 3161.26,1051.86 3182.77,1073.37 3430.62,1073.37 3509.52,1152.27 4301.7,1152.27 4334.54,1119.43 4354.32,1119.43 4363.29,1128.4 4613.79,1128.4 4622.04,1120.14 5042.65,1120.14 5071.39,1091.4 5096.26,1091.4 v2(5098.39,1089.27) ; v2(5105.44,1398.51) 5107.73,1400.81 5107.73,1421.28 5117.43,1430.98 5247.8,1561.35 5247.8,1599.09 5249.26,1600.55 5249.26,1619.41 5279.95,1650.09 5590.5,1650.09 5598.04,1642.55 5598.04,1640.09 5612.72,1625.41 R220.2@5616.66,1625.41
VSN2: C134.1 R222.2 R223.2 U25.59 | length 2914
  Top Layer w10: v2(2952.64,1076.31) 2972.32,1056.63 U25.59@2972.32,1006.16 ; v2(5037.86,974.58) 5037.86,1114.69 5049.95,1126.77 5049.95,1502.54 5054.15,1502.54 5066.75,1515.14 v2(5070,1515.14)
  Bottom Layer w10: C134.1@2946.91,1066.83 2947.09,1066.83 2950.85,1070.59 C134.1@2950.85,1074.53 ; v2(2952.64,1076.31) C134.1@2950.85,1074.53 ; v2(5037.86,974.58) 4996.76,1015.69 4647.26,1015.69 4585.68,1077.27 4101.27,1077.27 4062.02,1116.52 3851.73,1116.52 3812.48,1077.27 3483.86,1077.27 3455.74,1049.14 3216.39,1049.14 3192.2,1024.96 3008.59,1024.96 2963.23,1070.31 2961.89,1070.31 2957.67,1074.53 C134.1@2950.85,1074.53 ; v2(5070,1515.14) 5070,1518.39 5081.13,1529.52 5081.13,1563.92 R223.2@5086.71,1569.5
VSN3: C135.1 R224.2 R225.2 U25.22 | length 3494.4
  Top Layer w10: U25.22@2972.32,659.7 2972.32,653.17 2972.04,652.89 v2(2972.04,566.25) R224.2@2972.44,565.85 ; v2(3606.06,1536.65) 3607.54,1538.12 3812.63,1538.12 3845.94,1504.82 3926.25,1504.82 3927.25,1505.82 4225.05,1505.82 4226.05,1504.82 4272.66,1504.82 4304.49,1536.65 4399.17,1536.65 4453.17,1482.64 v2(4831.1,1482.64)
  Int3 (Signal) w10: v2(2972.04,566.25) 2974.34,563.95 2974.34,476.5 2995.91,454.92 3591.96,454.92 3623.66,486.62 3623.66,934.29 3542.27,1015.68 3542.27,1329.07 3607.23,1394.03 3607.23,1535.48 v2(3606.06,1536.65)
  Bottom Layer w10: v2(4831.1,1482.64) 4977.74,1482.64 5026.16,1531.06 R225.2@5026.16,1567.11
VSN4: C136.1 R227.2 R230.2 U25.27 | length 2344.8
  Top Layer w8: U25.27@3070.75,659.7 R230.2@3070.75,589.25 3070.75,581 v2(3072.65,579.1)
  Top Layer w10: v2(3741.32,735.57) 3883.3,735.57 3889.26,729.61 4103.1,729.61 4116.95,743.46 v2(4163.59,743.46)
  Int3 (Signal) w10: v2(4163.59,743.46) 4162,745.05 4162,876.78 4265.99,980.77 4265.99,1528.93 4274.86,1537.8 v2(4274.86,1540.79)
  Int1 (PGND) w8: v2(3072.65,579.1) 3106.57,579.1 3115.83,569.84 3479.24,569.84 3644.97,735.57 v2(3741.32,735.57)
  Bottom Layer w10: v2(4274.86,1540.79) 4276.01,1541.94 4299.26,1541.94 4322.89,1565.56 4506.06,1565.56 R227.2@4510,1569.5
VSNS_SEL1: R240.1 U25.48 | length 118.4
  Top Layer w10: U25.48@3194.76,980.57 3201.3,980.57 3212.06,991.33 3212.06,992.7 3212.64,993.28 v2(3216.74,993.28)
  Bottom Layer w10: 3237.26,990.98 3219.03,990.98 v2(3216.74,993.28) 3245.72,993.28 3251.22,998.78 3278.59,998.78 R240.1@3281.97,1002.16
VSNS_SEL2: R242.1 U25.1 | length 67.9
  Top Layer w10: v2(2817.93,984.4) 2821.18,984.4 2824.73,980.85 2848.03,980.85 U25.1@2848.31,980.57
  Bottom Layer w10: R242.1@2783.62,980.57 2785.54,982.49 2816.01,982.49 v2(2817.93,984.4)
VSNS_SEL3: R252.1 U25.16 | length 111.6
  Top Layer w10: v2(2778.62,650.64) 2807.11,650.64 U25.16@2841.5,685.02
  Bottom Layer w10: v2(2778.62,650.64) R252.1@2778.62,685.14
VSNS_SEL4: R253.1 U25.33 | length 345
  Top Layer w10: U25.33@3194.76,685.29 3221.57,685.29 3233.44,673.43 3233.44,672.47 3251.42,654.49 3258.2,654.49 3261.23,651.46 3308.47,651.46 3328.55,651.46 3354.69,625.32 3354.69,623.91 3370,608.6 v2(3370,605.35)
  Bottom Layer w10: R253.1@3268.98,679.83 3272.91,679.83 3287.6,665.15 3287.6,662.69 3344,606.29 3369.06,606.29 v2(3370,605.35)
VSP1: C133.2 U25.51 U26.14 | length 961.5
  Top Layer w10: v2(2675.92,1165.62) 2675.92,1400.38 2743.31,1467.77 U26.14@2786.82,1467.77 ; U25.51@3129.8,1006.16 3130.08,1006.44 3130.08,1030.86 3148.05,1048.83 v2(3148.05,1075.73)
  Bottom Layer w10: v2(2675.92,1165.62) 2676.87,1165.62 2737.66,1104.83 3117.62,1104.83 3125.16,1097.29 3125.16,1094.83 3144.25,1075.73 v2(3148.05,1075.73)
VSP2: C134.2 U25.62 U26.15 | length 628.5
  Top Layer w10: U26.15@2786.82,1493.36 2790.68,1497.22 2825.33,1497.22 2828.23,1500.12 v2(2831.47,1500.12) ; v2(2870,1210.14) 2867.7,1207.85 2867.7,1199.36 2867.67,1199.33 2867.67,1080 2866.73,1079.06 2866.73,1070.57 v2(2864.43,1068.28) 2867.68,1068.28 2873.68,1062.28 2877.55,1062.28 2912.99,1026.83 2912.99,1006.44 U25.62@2913.27,1006.16
  Bottom Layer w10: v2(2831.47,1500.12) 2831.47,1498.62 2821.12,1488.26 2821.12,1259.03 v2(2870,1210.14) ; v2(2864.43,1068.28) 2865.16,1067.55 2898.95,1067.55 C134.2@2899.67,1066.83
VSP3: C135.2 U25.19 U27.14 | length 1315.8
  Top Layer w8: v2(2911.3,560.14) 2909.57,561.88 2909.57,583.14 2902.32,590.39 2902.32,632.41 2912.99,643.08 2912.99,659.43 U25.19@2913.27,659.7
  Top Layer w10: v2(2632.23,681.68) 2632.23,864.28 2672.34,904.39 2672.34,1071.53 2887.36,1286.55 2887.36,1390.98 2893.22,1396.84 2927.85,1396.84 U27.14@2929.76,1398.76
  Bottom Layer w10: v2(2632.23,681.68) 2633.4,680.51 2655.63,680.51 2703.32,632.82 2703.32,631.11 2710.29,624.14 2710.29,591.89 2742.03,560.14 C135.2@2909.33,560.14
VSP4: C136.2 U25.30 U27.15 | length 1077.3
  Top Layer w8: U27.15@2929.76,1373.17 2966.37,1373.17 2971.09,1377.89 2971.29,1377.89 2982.65,1389.25 3012.33,1389.25 3053.92,1347.66 v2(3079.5,1347.66) ; v2(3129.8,592.72) 3130.33,593.24 3130.33,610.24 3136.18,616.1 3136.18,635.05 3130.53,640.7 3130.53,658.98 U25.30@3129.8,659.7
  Int3 (Signal) w8: v2(3079.5,1347.66) 3079.5,1093.05 3023.66,1037.21 3023.66,682.87 3111.13,595.4 3127.13,595.4 v2(3129.8,592.72)
pads on no net: FID1.1 FID2.1 FID3.1 H1.1 H2.1 H3.1 H4.1 H5.0 H6.0 H7.0 H8.0 J11.1 J11.2 J11.3 J11.4 J11.5 J11.6 J11.8 J11.9 J11.11 J11.14 J11.17 J11.20 J11.23 J11.24 J11.26 J11.27 J11.32 J11.34 J11.36 J11.40 J11.41 J11.42 J11.43 J11.44 J11.58 J11.60 J11.62 J11.63 J11.64 J11.66 J11.67 J11.76 J11.78 J11.80 J11.82 J11.86 J11.88 J11.89 J11.90 J11.91 J11.92 J11.93 J11.94 J11.95 J11.106 J11.113 J11.114 J11.115 J11.116 J11.117 J11.118 J11.119 J11.120 J11.181 J11.182 J11.185 J11.186 J12.61 J12.62 J12.121 J12.122 J12.123 J12.124 J12.125 J12.126 J12.127 J12.128 J12.129 J12.130 J12.131 J12.132 J12.133 J12.134 J12.136 J12.137 J12.138 J12.139 J12.140 J12.141 J12.142 J12.143 J12.144 J12.145 J12.146 J12.147 J12.148 J12.149 J12.150 J12.151 J12.152 J12.153 J12.154 J12.155 J12.156 J12.159 J12.160 J12.161 J12.162 J12.163 J12.164 J12.165 J12.166 J12.167 J12.168 J12.169 J12.170 J12.171 J12.172 J12.173 J12.174 J12.175 J12.176 J12.177 J12.178 LBL1.0 Q1_1.9@4825.59,4449.14 Q1_1.9@4866.64,4346.98 Q1_1.9@4866.64,4392.25 Q1_1.9@4866.64,4437.53 Q1_1.9@4919,4346.98 Q1_1.9@4919,4386.94 Q1_1.9@4919,4392.25 Q1_1.9@4919,4437.53 Q1_1.9@4971.36,4346.98 Q1_1.9@4971.36,4392.25 Q1_1.9@4971.36,4437.53 Q1_1.9@5012.41,4449.14 Q1_2.9@3397.59,4453.15 Q1_2.9@3438.64,4350.98 Q1_2.9@3438.64,4396.26 Q1_2.9@3438.64,4441.53 Q1_2.9@3491,4350.98 Q1_2.9@3491,4390.94 Q1_2.9@3491,4396.26 Q1_2.9@3491,4441.53 Q1_2.9@3543.36,4350.98 Q1_2.9@3543.36,4396.26 Q1_2.9@3543.36,4441.53 Q1_2.9@3584.41,4453.15 Q1_3.9@1900.99,4464.75 Q1_3.9@1942.03,4362.59 Q1_3.9@1942.03,4407.86 Q1_3.9@1942.03,4453.14 Q1_3.9@1994.39,4362.59 Q1_3.9@1994.39,4402.55 Q1_3.9@1994.39,4407.86 Q1_3.9@1994.39,4453.14 Q1_3.9@2046.75,4362.59 Q1_3.9@2046.75,4407.86 Q1_3.9@2046.75,4453.14 Q1_3.9@2087.8,4464.75 Q1_4.9@500.59,4476.08 Q1_4.9@541.64,4373.92 Q1_4.9@541.64,4419.19 Q1_4.9@541.64,4464.47 Q1_4.9@594,4373.92 Q1_4.9@594,4413.88 Q1_4.9@594,4419.19 Q1_4.9@594,4464.47 Q1_4.9@646.36,4373.92 Q1_4.9@646.36,4419.19 Q1_4.9@646.36,4464.47 Q1_4.9@687.41,4476.08 Q2_1.9@4825.59,4690.88 Q2_1.9@4866.64,4702.49 Q2_1.9@4866.64,4747.77 Q2_1.9@4866.64,4793.04 Q2_1.9@4919,4702.49 Q2_1.9@4919,4747.77 Q2_1.9@4919,4753.08 Q2_1.9@4919,4793.04 Q2_1.9@4971.36,4702.49 Q2_1.9@4971.36,4747.77 Q2_1.9@4971.36,4793.04 Q2_1.9@5012.41,4690.88 Q2_2.9@3397.59,4694.88 Q2_2.9@3438.64,4706.49 Q2_2.9@3438.64,4751.77 Q2_2.9@3438.64,4797.04 Q2_2.9@3491,4706.49 Q2_2.9@3491,4751.77 Q2_2.9@3491,4757.08 Q2_2.9@3491,4797.04 Q2_2.9@3543.36,4706.49 Q2_2.9@3543.36,4751.77 Q2_2.9@3543.36,4797.04 Q2_2.9@3584.41,4694.88 Q2_3.9@1900.99,4706.49 Q2_3.9@1942.03,4718.1 Q2_3.9@1942.03,4763.38 Q2_3.9@1942.03,4808.65 Q2_3.9@1994.39,4718.1 Q2_3.9@1994.39,4763.38 Q2_3.9@1994.39,4768.69 Q2_3.9@1994.39,4808.65 Q2_3.9@2046.75,4718.1 Q2_3.9@2046.75,4763.38 Q2_3.9@2046.75,4808.65 Q2_3.9@2087.8,4706.49 Q2_4.9@500.59,4717.81 Q2_4.9@541.64,4729.43 Q2_4.9@541.64,4774.7 Q2_4.9@541.64,4819.98 Q2_4.9@594,4729.43 Q2_4.9@594,4774.7 Q2_4.9@594,4780.02 Q2_4.9@594,4819.98 Q2_4.9@646.36,4729.43 Q2_4.9@646.36,4774.7 Q2_4.9@646.36,4819.98 Q2_4.9@687.41,4717.81 Q3_1.9@5163.96,4448.14 Q3_1.9@5205,4345.98 Q3_1.9@5205,4391.25 Q3_1.9@5205,4436.53 Q3_1.9@5257.36,4345.98 Q3_1.9@5257.36,4385.94 Q3_1.9@5257.36,4391.25 Q3_1.9@5257.36,4436.53 Q3_1.9@5309.72,4345.98 Q3_1.9@5309.72,4391.25 Q3_1.9@5309.72,4436.53 Q3_1.9@5350.77,4448.14 Q3_2.9@3735.96,4452.15 Q3_2.9@3777,4349.98 Q3_2.9@3777,4395.26 Q3_2.9@3777,4440.53 Q3_2.9@3829.36,4349.98 Q3_2.9@3829.36,4389.94 Q3_2.9@3829.36,4395.26 Q3_2.9@3829.36,4440.53 Q3_2.9@3881.72,4349.98 Q3_2.9@3881.72,4395.26 Q3_2.9@3881.72,4440.53 Q3_2.9@3922.77,4452.15 Q3_3.9@2239.35,4463.75 Q3_3.9@2280.39,4361.59 Q3_3.9@2280.39,4406.86 Q3_3.9@2280.39,4452.14 Q3_3.9@2332.75,4361.59 Q3_3.9@2332.75,4401.55 Q3_3.9@2332.75,4406.86 Q3_3.9@2332.75,4452.14 Q3_3.9@2385.12,4361.59 Q3_3.9@2385.12,4406.86 Q3_3.9@2385.12,4452.14 Q3_3.9@2426.16,4463.75 Q3_4.9@838.96,4475.08 Q3_4.9@880,4372.92 Q3_4.9@880,4418.19 Q3_4.9@880,4463.47 Q3_4.9@932.36,4372.92 Q3_4.9@932.36,4412.88 Q3_4.9@932.36,4418.19 Q3_4.9@932.36,4463.47 Q3_4.9@984.72,4372.92 Q3_4.9@984.72,4418.19 Q3_4.9@984.72,4463.47 Q3_4.9@1025.77,4475.08 Q4_1.9@5163.96,4689.88 Q4_1.9@5205,4701.49 Q4_1.9@5205,4746.77 Q4_1.9@5205,4792.04 Q4_1.9@5257.36,4701.49 Q4_1.9@5257.36,4746.77 Q4_1.9@5257.36,4752.08 Q4_1.9@5257.36,4792.04 Q4_1.9@5309.72,4701.49 Q4_1.9@5309.72,4746.77 Q4_1.9@5309.72,4792.04 Q4_1.9@5350.77,4689.88 Q4_2.9@3735.96,4693.88 Q4_2.9@3777,4705.49 Q4_2.9@3777,4750.77 Q4_2.9@3777,4796.04 Q4_2.9@3829.36,4705.49 Q4_2.9@3829.36,4750.77 Q4_2.9@3829.36,4756.08 Q4_2.9@3829.36,4796.04 Q4_2.9@3881.72,4705.49 Q4_2.9@3881.72,4750.77 Q4_2.9@3881.72,4796.04 Q4_2.9@3922.77,4693.88 Q4_3.9@2239.35,4705.49 Q4_3.9@2280.39,4717.1 Q4_3.9@2280.39,4762.38 Q4_3.9@2280.39,4807.65 Q4_3.9@2332.75,4717.1 Q4_3.9@2332.75,4762.38 Q4_3.9@2332.75,4767.69 Q4_3.9@2332.75,4807.65 Q4_3.9@2385.12,4717.1 Q4_3.9@2385.12,4762.38 Q4_3.9@2385.12,4807.65 Q4_3.9@2426.16,4705.49 Q4_4.9@838.96,4716.81 Q4_4.9@880,4728.43 Q4_4.9@880,4773.7 Q4_4.9@880,4818.98 Q4_4.9@932.36,4728.43 Q4_4.9@932.36,4773.7 Q4_4.9@932.36,4779.02 Q4_4.9@932.36,4818.98 Q4_4.9@984.72,4728.43 Q4_4.9@984.72,4773.7 Q4_4.9@984.72,4818.98 Q4_4.9@1025.77,4716.81 SH-J2.0 SH-J3.0 SH-J4.0 SH-J5.0 U1_1.1 U1_1.5 U1_1.10 U1_1.11 U1_1.12 U1_1.13 U1_1.15 U1_2.1 U1_2.5 U1_2.10 U1_2.11 U1_2.12 U1_2.13 U1_2.15 U1_3.1 U1_3.5 U1_3.10 U1_3.11 U1_3.12 U1_3.13 U1_3.15 U1_4.1 U1_4.5 U1_4.10 U1_4.11 U1_4.12 U1_4.13 U1_4.15 U2_1.1 U2_1.5 U2_1.11 U2_1.12 U2_1.13 U2_1.15 U2_2.1 U2_2.5 U2_2.11 U2_2.12 U2_2.13 U2_2.15 U2_3.1 U2_3.5 U2_3.11 U2_3.12 U2_3.13 U2_3.15 U2_4.1 U2_4.5 U2_4.11 U2_4.12 U2_4.13 U2_4.15 U3_1.1 U3_1.5 U3_1.8 U3_1.9 U3_1.10 U3_1.11 U3_1.12 U3_1.13 U3_1.14 U3_1.15 U3_2.1 U3_2.5 U3_2.8 U3_2.9 U3_2.10 U3_2.11 U3_2.12 U3_2.13 U3_2.14 U3_2.15 U3_3.1 U3_3.5 U3_3.8 U3_3.9 U3_3.10 U3_3.11 U3_3.12 U3_3.13 U3_3.14 U3_3.15 U3_4.1 U3_4.5 U3_4.8 U3_4.9 U3_4.10 U3_4.11 U3_4.12 U3_4.13 U3_4.14 U3_4.15 U5_1.7@4665.39,4369.98 U5_1.7@4665.39,4405.41 U5_2.7@3239.46,4285.37 U5_2.7@3239.46,4320.8 U5_3.7@1740,4283.38 U5_3.7@1740,4318.81 U5_4.7@340,4292.77 U5_4.7@340,4328.2 U9.1 U9.5 U10.15 U10.25 U11.3 U11.7 U11.8 U16.1 U16.6 U16.7 U17.4 U25.6 U25.8 U25.12 U25.37 U26.3 U26.4 U26.5 U26.9 U27.3 U27.4 U27.5 U27.9
copper on no net: | length 0.1
  Top Layer w10: 5498.46,945.54 5498.54,945.62

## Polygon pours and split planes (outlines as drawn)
AGND on Top Layer "TOP_LAYER_AGND_P501" (solid, remove dead copper, pour order 501): 1571.84,39.35 1571.84,71.66 1571.84,1929.41 6350.52,1929.41 6380,1899.93 6380,50.14
NetC11_3_1 on Top Layer "TOP_LAYER_NETC11_3_1_P386" (solid, remove dead copper, pour order 386): 2264.4,4045.64 2264.4,3844.73 2605.5,3844.73 2605.5,3728.84 2605.5,3204.73 1778.93,3204.73 1778.93,3434.73 1964.81,3434.73 1985.01,3454.93 1985.01,3759.02 1778.93,3759.02 1778.93,4045.64
PGND on Top Layer "TOP_LAYER_PGND_P495" (solid, remove dead copper, pour order 495): 40,40.14 1860,40.14 1860,927.04 1827.96,959.08 1628.98,959.08 1586.38,1001.68 1590.72,1006.03 1590.72,1902.34 6397.8,1902.34 6399.8,1900.35 6399.8,5770.82 40.67,5770.82 40,5770.14
PGND on Top Layer "TOP_LAYER_PGND_P406" (solid, remove dead copper, pour order 406): 18 vertices, not listed, extent 1036.38,2341.61 1706.38,5789.66
PGND on Top Layer "TOP_LAYER_PGND_P405" (solid, remove dead copper, pour order 405): 18 vertices, not listed, extent 5385,2316.61 6055,5764.66
OUTP3 on Top Layer "TOP_LAYER_OUTP3_P391" (solid, remove dead copper, pour order 391): 2237.44,4209.61 2385.52,4209.61 2387.44,4218.86 2385.52,4219.63 2385.52,4479.48 2380.52,4484.48 1775.39,4484.48 1775.39,4059.48 2237.44,4059.48
PGND on Top Layer "TOP_LAYER_PGND_P404" (solid, remove dead copper, pour order 404): 18 vertices, not listed, extent 2460.39,2332.22 3130.39,5780.26
PGND on Top Layer "TOP_LAYER_PGND_P441" (solid, remove dead copper, pour order 441): 18 vertices, not listed, extent 3957,2320.61 4627,5768.66
Source_1 on Top Layer "TOP_LAYER_SOURCE_1_P487" (solid, remove dead copper, pour order 487): 4700,4670.87 5376.2,4670.87 5376.2,4476.54 4700,4476.54
Source_4 on Top Layer "TOP_LAYER_SOURCE_4_P486" (solid, remove dead copper, pour order 486): 375,4699.87 1040.44,4699.87 1040.44,4505.54 375,4505.54
NetC74_2 on Top Layer "TOP_LAYER_NETC74_2_P479" (solid, remove dead copper, pour order 479): 1491.93,411.88 1573.49,411.88 1636.76,475.14 1712.05,475.14 1712.05,260.99 1701.16,250.1 1587.46,250.1 1578.7,241.35 1578.7,175.18 1491.93,175.18
NetC72_2 on Top Layer "TOP_LAYER_NETC72_2_P474" (solid, remove dead copper, pour order 474): 1172.83,358.96 1225.75,411.88 1441.28,411.88 1441.28,170.14 1340.28,170.14 1340.28,339.28 1329.45,350.11 1170.87,350.11
NetC73_2 on Top Layer "TOP_LAYER_NETC73_2_P473" (solid, remove dead copper, pour order 473): 1301.96,740.93 1324.83,763.81 1587.8,763.81 1587.8,533.4 1507.83,533.4 1495.75,545.49 1495.75,696.65 1460.98,696.65 1433.56,724.07 1301.79,724.07 1301.23,723.52
V_HV_4 on Top Layer "TOP_LAYER_V_HV_4_P472" (solid, remove dead copper, pour order 472): 25 vertices, not listed, extent 378.54,1953.05 1193.23,2548.03
SW_4 on Top Layer "TOP_LAYER_SW_4_P464" (solid, remove dead copper, pour order 464): 23 vertices, not listed, extent 378.54,2355.27 1314.89,3196.45
V_HV on Top Layer "TOP_LAYER_V_HV_P462" (solid, remove dead copper, pour order 462): 17 vertices, not listed, extent 45,1095.14 5509.81,1920.14
OUTP4 on Top Layer "TOP_LAYER_OUTP4_P392" (solid, remove dead copper, pour order 392): 837.05,4219 985.13,4219 987.05,4228.25 985.13,4229.02 985.13,4488.87 980.13,4493.87 375,4493.87 375,4068.87 837.05,4068.87
BATP_4 on Top Layer "TOP_LAYER_BATP_4_P402" (solid, remove dead copper, pour order 402): 1055,4705.27 375,4705.27 375,5793.65 1055,5793.65
NetC11_4_1 on Top Layer "TOP_LAYER_NETC11_4_1_P388" (solid, remove dead copper, pour order 388): 864.01,4055.03 864.01,3854.12 1205.11,3854.12 1205.11,3738.24 1205.11,3214.12 378.54,3214.12 378.54,3444.12 564.42,3444.12 584.62,3464.32 584.62,3768.41 378.54,3768.41 378.54,4055.03
BATP_3 on Top Layer "TOP_LAYER_BATP_3_P401" (solid, remove dead copper, pour order 401): 5380,4680.27 4700,4680.27 4700,5768.65 5380,5768.65
NetC11_1_1 on Top Layer "TOP_LAYER_NETC11_1_1_P387" (solid, remove dead copper, pour order 387): 5189.01,4030.03 5189.01,3829.12 5530.11,3829.12 5530.11,3713.24 5530.11,3189.12 4703.54,3189.12 4703.54,3419.12 4889.42,3419.12 4909.62,3439.32 4909.62,3743.41 4703.54,3743.41 4703.54,4030.03
V_HV_1 on Top Layer "TOP_LAYER_V_HV_1_P383" (solid, remove dead copper, pour order 383): 25 vertices, not listed, extent 4703.54,1930.27 5518.23,2525.24
SW_3 on Top Layer "TOP_LAYER_SW_3_P378" (solid, remove dead copper, pour order 378): 23 vertices, not listed, extent 1778.93,2355.87 2715.28,3197.06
